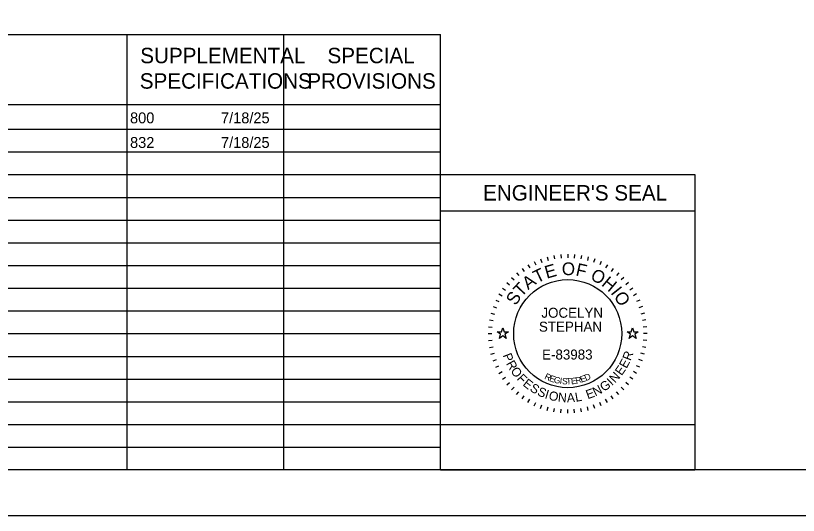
# Model space of a CAD drawing. Extents: x 0 to 34, y 0 to 22.
# Drawn here: x 20.02 to 28.64, y 0 to 5.5 of the extents above; entities that cross this region are included whole.
import ezdxf

# ---------------------------------------------------------------- set-up
doc = ezdxf.new("R2010")
doc.units = 0
for name, color, linetype in [('SH_Border', 7, 'Continuous'), ('SH_Cut_Line', 7, 'Continuous'), ('SH_Data', 7, 'Continuous'), ('SH_Seal', 7, 'Continuous'), ('SH_Text', 7, 'Continuous')]:
    doc.layers.add(name, color=color, linetype=linetype)

msp = doc.modelspace()

# ---------------------------------------------------------------- linework, layer by layer
at = {"layer": 'SH_Border'}
msp.add_lwpolyline([(1.5, 21.5), (33.5, 21.5), (33.5, 0.5), (1.5, 0.5)], close=True, dxfattribs=at)
at = {"layer": 'SH_Cut_Line'}
msp.add_lwpolyline([(0, 0), (34, 0), (34, 22), (0, 22)], close=True, dxfattribs=at)
at = {"layer": 'SH_Data'}
for p, q in [((11.25, 5.2917), (24.7, 5.2917)), ((21.25, 0.5), (21.25, 5.2917)), ((22.975, 0.5), (22.975, 5.2917)), ((24.7, 0.5), (24.7, 5.2917)), ((11.25, 4.5209), (24.7, 4.5209)), ((11.25, 4.25), (24.7, 4.25)), ((11.25, 4), (24.7, 4)), ((11.25, 3.75), (24.7, 3.75)), ((24.7, 0.5), (24.7, 3.75)), ((24.7, 3.75), (27.5, 3.75)), ((24.7, 0.5), (24.7, 3.75)), ((24.7, 3.75), (27.5, 3.75)), ((27.5, 3.75), (27.5, 0.5)), ((27.5, 3.75), (27.5, 0.5)), ((11.25, 3.5), (24.7, 3.5)), ((24.7, 3.35), (27.5, 3.35)), ((24.7, 3.35), (27.5, 3.35)), ((11.25, 3.25), (24.7, 3.25)), ((11.25, 3), (24.7, 3)), ((11.25, 2.75), (24.7, 2.75)), ((11.25, 2.5), (24.7, 2.5)), ((11.25, 2.25), (24.7, 2.25)), ((11.25, 2), (24.7, 2)), ((11.25, 1.75), (24.7, 1.75)), ((11.25, 1.5), (24.7, 1.5)), ((11.25, 1.25), (24.7, 1.25)), ((11.25, 1), (24.7, 1)), ((11.25, 0.75), (24.7, 0.75)), ((24.7, 0.5), (27.5, 0.5))]:
    msp.add_line(p, q, dxfattribs=at)
msp.add_lwpolyline([(24.7, 0.5), (24.7, 1), (27.5, 1), (27.5, 0.5)], close=True, dxfattribs=at)
msp.add_lwpolyline([(24.7, 0.5), (24.7, 1), (27.5, 1), (27.5, 0.5)], close=True, dxfattribs=at)
at = {"layer": 'SH_Seal'}
for p, q in [((25.8735, 2.8452), (25.8839, 2.8065)), ((25.9481, 2.8617), (25.955, 2.8223)), ((26.0237, 2.8717), (26.0272, 2.8318)), ((26.1, 2.875), (26.1, 2.835)), ((26.1763, 2.8717), (26.1728, 2.8318)), ((26.2519, 2.8617), (26.245, 2.8223)), ((26.3265, 2.8452), (26.3161, 2.8065)), ((25.7302, 2.793), (25.7471, 2.7568)), ((25.8007, 2.8222), (25.8144, 2.7846)), ((26.3993, 2.8222), (26.3856, 2.7846)), ((26.4698, 2.793), (26.4529, 2.7568)), ((25.5981, 2.7168), (25.6211, 2.684)), ((25.6625, 2.7578), (25.6825, 2.7231)), ((26.5375, 2.7578), (26.5175, 2.7231)), ((26.6019, 2.7168), (26.5789, 2.684)), ((25.4813, 2.6187), (25.5096, 2.5904)), ((25.5376, 2.6703), (25.5633, 2.6396)), ((26.6624, 2.6703), (26.6367, 2.6396)), ((26.7187, 2.6187), (26.6904, 2.5904)), ((25.3832, 2.5019), (25.416, 2.4789)), ((25.4297, 2.5624), (25.4604, 2.5367)), ((26.7703, 2.5624), (26.7396, 2.5367)), ((26.8168, 2.5019), (26.784, 2.4789)), ((25.3422, 2.4375), (25.3769, 2.4175)), ((26.8578, 2.4375), (26.8231, 2.4175)), ((25.307, 2.3698), (25.3432, 2.3529)), ((26.893, 2.3698), (26.8568, 2.3529)), ((25.2778, 2.2993), (25.3154, 2.2856)), ((26.9222, 2.2993), (26.8846, 2.2856)), ((25.2548, 2.2265), (25.2935, 2.2161)), ((26.9452, 2.2265), (26.9065, 2.2161)), ((25.2283, 2.0763), (25.2682, 2.0728)), ((25.2383, 2.1519), (25.2777, 2.145)), ((26.9617, 2.1519), (26.9223, 2.145)), ((26.9717, 2.0763), (26.9318, 2.0728)), ((25.225, 2), (25.265, 2)), ((26.975, 2), (26.935, 2)), ((25.2283, 1.9237), (25.2682, 1.9272)), ((26.9717, 1.9237), (26.9318, 1.9272)), ((25.2383, 1.8481), (25.2777, 1.855)), ((26.9617, 1.8481), (26.9223, 1.855)), ((25.2548, 1.7735), (25.2935, 1.7839)), ((26.9452, 1.7735), (26.9065, 1.7839)), ((25.2778, 1.7007), (25.3154, 1.7144)), ((25.307, 1.6302), (25.3432, 1.6471)), ((26.893, 1.6302), (26.8568, 1.6471)), ((26.9222, 1.7007), (26.8846, 1.7144)), ((25.3422, 1.5625), (25.3769, 1.5825)), ((26.8578, 1.5625), (26.8231, 1.5825)), ((25.3832, 1.4981), (25.416, 1.5211)), ((26.8168, 1.4981), (26.784, 1.5211)), ((25.4297, 1.4376), (25.4604, 1.4633)), ((25.4813, 1.3813), (25.5096, 1.4096)), ((26.7187, 1.3813), (26.6904, 1.4096)), ((26.7703, 1.4376), (26.7396, 1.4633)), ((25.5376, 1.3297), (25.5633, 1.3604)), ((25.5981, 1.2832), (25.6211, 1.316)), ((26.6019, 1.2832), (26.5789, 1.316)), ((26.6624, 1.3297), (26.6367, 1.3604)), ((25.6625, 1.2422), (25.6825, 1.2769)), ((25.7302, 1.207), (25.7471, 1.2432)), ((25.8007, 1.1778), (25.8144, 1.2154)), ((26.3993, 1.1778), (26.3856, 1.2154)), ((26.4698, 1.207), (26.4529, 1.2432)), ((26.5375, 1.2422), (26.5175, 1.2769)), ((25.8735, 1.1548), (25.8839, 1.1935)), ((25.9481, 1.1383), (25.955, 1.1777)), ((26.0237, 1.1283), (26.0272, 1.1682)), ((26.1, 1.125), (26.1, 1.165)), ((26.1763, 1.1283), (26.1728, 1.1682)), ((26.2519, 1.1383), (26.245, 1.1777)), ((26.3265, 1.1548), (26.3161, 1.1935))]:
    msp.add_line(p, q, dxfattribs=at)
for points in [[(25.3236, 2.02), (25.3705, 2.02), (25.385, 2.0645), (25.3995, 2.02), (25.4464, 2.02), (25.4085, 1.9924), (25.423, 1.9478), (25.385, 1.9754), (25.347, 1.9478), (25.3615, 1.9924)], [(26.7536, 2.02), (26.8005, 2.02), (26.815, 2.0645), (26.8295, 2.02), (26.8764, 2.02), (26.8385, 1.9924), (26.853, 1.9478), (26.815, 1.9754), (26.777, 1.9478), (26.7915, 1.9924)]]:
    msp.add_lwpolyline(points, close=True, dxfattribs=at)
msp.add_circle((26.1, 2), 0.595, dxfattribs=at)

# ---------------------------------------------------------------- texts
at = {"layer": 'SH_Data'}
msp.add_text("ENGINEER'S SEAL", height=0.17, dxfattribs=at).set_placement((25.1676, 3.465))
msp.add_text("ENGINEER'S SEAL", height=0.17, dxfattribs=at).set_placement((25.1676, 3.465))
at = {"layer": 'SH_Seal'}
for s, height, rotation, p in [('E', 0.14, 15.75706, (25.8684, 2.6038)), ('O', 0.14, 359.78119, (26.0347, 2.6443)), ('F', 0.14, 347.43619, (26.1811, 2.6417)), ('T', 0.14, 25.71674, (25.7616, 2.5518)), ('O', 0.14, 332.25863, (26.3398, 2.6015)), ('A', 0.14, 36.47472, (25.6634, 2.4781)), ('H', 0.14, 319.91363, (26.4632, 2.5361)), ('T', 0.14, 46.4344, (25.5883, 2.3964)), ('I', 0.14, 308.36695, (26.5665, 2.4483)), ('S', 0.14, 57.19238, (25.5281, 2.3014)), ('O', 0.14, 303.14906, (26.6021, 2.4089)), ('P', 0.1, 291.49398, (25.3823, 1.7621)), ('E', 0.1, 61.99508, (26.7476, 1.6098)), ('R', 0.1, 69.23216, (26.7919, 1.6954)), ('R', 0.1, 298.73106, (25.419, 1.6717)), ('E', 0.1, 54.75801, (26.6933, 1.5314)), ('O', 0.1, 306.46664, (25.4655, 1.5883)), ('F', 0.1, 314.7068, (25.5343, 1.4983)), ('R', 0.07, 334.48695, (25.8375, 1.5051)), ('D', 0.07, 23.30524, (26.301, 1.477)), ('N', 0.1, 47.02243, (26.6202, 1.4508)), ('E', 0.1, 321.43929, (25.5978, 1.4348)), ('E', 0.07, 341.03996, (25.8906, 1.4801)), ('G', 0.07, 347.47515, (25.9414, 1.4618)), ('I', 0.07, 353.78581, (26.0091, 1.4468)), ('S', 0.07, 356.89262, (26.0358, 1.4429)), ('T', 0.07, 3.00609, (26.0857, 1.4387)), ('E', 0.07, 6.01169, (26.1389, 1.4412)), ('R', 0.07, 11.91844, (26.1925, 1.4474)), ('E', 0.07, 17.68363, (26.2498, 1.4602)), ('G', 0.1, 35.04687, (26.4981, 1.357)), ('I', 0.1, 43.28703, (26.5868, 1.4214)), ('S', 0.1, 328.67637, (25.6743, 1.3752)), ('S', 0.1, 335.91345, (25.7564, 1.3266)), ('I', 0.1, 343.15053, (25.8406, 1.2897)), ('E', 0.1, 20.07421, (26.3212, 1.277)), ('N', 0.1, 27.31129, (26.4045, 1.3075)), ('O', 0.1, 346.88592, (25.8839, 1.2751)), ('N', 0.1, 355.12608, (25.9888, 1.2517)), ('A', 0.1, 2.86166, (26.0923, 1.2437)), ('L', 0.1, 10.09874, (26.1894, 1.249))]:
    msp.add_text(s, height=height, rotation=rotation, dxfattribs=at).set_placement(p)
for s, p in [('JOCELYN', (25.81, 2.1749)), ('STEPHAN', (25.7831, 2.0216)), ('E-83983', (25.8177, 1.7151))]:
    msp.add_text(s, height=0.11, dxfattribs=at).set_placement(p)
at = {"layer": 'SH_Text'}
for s, height, p in [('SUPPLEMENTAL', 0.17, (21.3925, 4.9763)), ('SPECIAL', 0.17, (23.4542, 4.9763)), ('SPECIFICATIONS', 0.17, (21.3871, 4.6963)), ('PROVISIONS', 0.17, (23.2323, 4.6963)), ('800     ', 0.12, (21.28, 4.315)), ('7/18/25', 0.12, (22.2818, 4.315)), ('832     ', 0.12, (21.28, 4.0441)), ('7/18/25', 0.12, (22.2818, 4.0441))]:
    msp.add_text(s, height=height, dxfattribs=at).set_placement(p)

doc.saveas('drawing.dxf')
